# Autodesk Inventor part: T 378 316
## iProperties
Company: Mayer & Müller AG Schaltgeräte
Created: 2005-12
Part Number: T 378 316
Material: HGW 2372.4
Document SubType Name: Modeling
Designer: I.Baliuc
Manufacturer: Standard
Standards Organization: Custom
Description: Anschlaghebel
Density: 1.38 g/cm^3
Zweck: für HSLT - Vorkontakt
Author: T.Messerschmitt
Revision Number: 378316
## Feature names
1. Extrusion2
2. Bohrung1 [Hole]
3. Bohrung2 [Hole]
